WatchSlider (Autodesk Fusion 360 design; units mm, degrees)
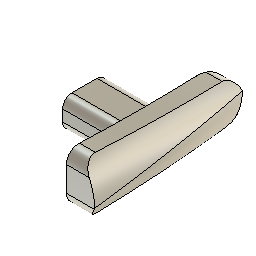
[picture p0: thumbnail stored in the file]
parameter "d65" = 4
sketch "Sketch1"
  line L1 (-0.2944, 8.4) -> (-0.2944, -8.4)
  line L2 (-2.6064, -5) -> (-2.6064, 5)
  line L3 (0, 0) -> (-120, 0)
  line L4 (2.7056, -8.4) -> (-0.2944, -8.4)
  line L5 (2.7056, 8.4) -> (-0.2944, 8.4)
  line L6 (-4.7, 1.75) -> (0, 1.75)
  line L7 (-4.7, -1.75) -> (-4.7, 1.75)
  line L8 (-0.0128, -1.75) -> (-4.7, -1.75)
  line L9 (-1.7, 0.75) -> (-4.7, 0.75)
  line L10 (-1.7, -0.75) -> (-1.7, 0.75)
  line L11 (-4.7, -0.75) -> (-1.7, -0.75)
  line L12 (0, 0) -> (-1.7, 0)
  line L13 (-1.7, 0) -> (-4.7, 0)
  arc A1 centre (-120, 0) radius 120 clockwise from (-0.2944, 8.4) to (-0.2944, -8.4)
  arc A2 centre (-120, 0) radius 117.5 clockwise from (-2.6064, 5) to (-2.6064, -5)
  arc A3 centre (-120, 0) radius 122.9928 clockwise from (2.7056, 8.4) to (2.7056, -8.4)
  circle C1 centre (-3.4, 0) radius 0.8
  circle C2 centre (-3.4, 0) radius 0.625
  point P2 (-0.2944, 8.4)
  point P3 (-0.2944, -8.4)
  point P5 (-2.6064, 5)
  point P6 (-2.6064, -5)
  point P18 (-1.7, 0.75)
  point P19 (-1.7, -0.75)
  point P20 (-4.7, -0.75)
  point P1 (0, 0)
  point P11 (2.7056, 8.4)
  dimension "d1" radius A1 = 120
  dimension "d2" distance A1 A2 = 2.5
  dimension "d3" distance P2 P3 = 16.8 (= "20 mm - 3.2 mm")
  dimension "d4" distance P5 P6 = 10
  dimension "d6" distance P18 P19 = 1.5
  dimension "d8" diameter C1 = 1.6
  dimension "d11" distance P19 P20 = 3
  dimension "d12" distance P1 L7 = 4.7
  dimension "d13" distance L6 L9 = 1
  dimension "d27" distance P2 P11 = 3
  dimension "d28" diameter C2 = 1.25
  dimension "d72" distance L7 C1 = 0.5
extrude "Extrude1" new body sketch "Sketch1" profile of A1 L6 L7 L8 L9 L10 L11 C1 distance 2.4
extrude "Extrude2" add sketch "Sketch1" profile of A1 L5 A3 distance 4
extrude "Extrude3" cut sketch "Sketch1" profile of L7 L9 L10 L11 C1 C2 distance 0.6
fillet "Fillet2" radius 0.75
sketch "Sketch4" plane through (0, -8.4, 0) normal (0, -1, 0) x axis (1, 0, 0)
  line L1 (2.7056, 2) -> (2.7056, -2)
  line L2 (-0.2944, 2) -> (2.7056, 2)
  line L3 (-0.2944, -2) -> (-0.2944, 2)
  line L4 (2.7056, -2) -> (-0.2944, -2)
  line L5 (1.4479, -2) -> (2.0264, -1.3106)
  line L6 (3.9, -2) -> (2.7056, -2)
  line L7 (3.9, 2) -> (3.9, -2)
  line L8 (2.7056, 2) -> (3.9, 2)
  arc A1 centre (-3.9717, -1.4642) radius 6 clockwise from (0.9273, 2) to (2.0264, -1.3106)
  point P6 (0.9273, 2)
  point P5 (-0.2944, -2)
  point P9 (1.4479, -2)
  point P7 (2.0264, -1.3106)
  dimension "d38" radius A1 = 6
  dimension "d39" distance L3 P6 = 1.2216
  dimension "d40" distance P5 P9 = 1.7422
  dimension "d41" angle L4 L5 = 50
  dimension "d42" distance P7 P9 = 0.9
sketch "Sketch5" plane through (0, 8.4, 0) normal (0, 1, 0) x axis (-1, 0, 0)
  line L1 (0.2944, 2) -> (0.2944, -2)
  line L2 (-2.7056, 2) -> (0.2944, 2)
  line L3 (-2.7056, -2) -> (-2.7056, 2)
  line L4 (0.2944, -2) -> (-2.7056, -2)
  line L5 (-1.2, 2) -> (-1.8, 1.6)
  line L6 (-3.9, 2) -> (-2.7056, 2)
  line L7 (-3.9, 2) -> (-3.9, -2)
  line L8 (-3.9, -2) -> (-3.9, 2)
  line L9 (-3.9, -2) -> (-2.7056, -2)
  arc A1 centre (3.5258, 1.6565) radius 5.3261 clockwise from (-0.3469, -2) to (-1.8, 1.6)
loft "Loft2" sketch "Sketch4" + "Sketch5"
extrude "Extrude4" cut sketch "Sketch1" profile of C2 no distance stored
sketch "Sketch6"
  line L1 (-0.2944, 6) -> (-0.2944, 8.4)
  line L2 (3.7056, 6) -> (-0.2944, 6)
  line L3 (3.7056, 8.4) -> (3.7056, 6)
  line L4 (-0.2944, 8.4) -> (3.7056, 8.4)
  line L5 (-0.2944, -6) -> (-0.2944, -8.4)
  line L6 (3.7056, -6) -> (-0.2944, -6)
  line L7 (3.7056, -8.4) -> (3.7056, -6)
  line L8 (-0.2944, -8.4) -> (3.7056, -8.4)
  point P2 (-0.2944, 8.4)
  point P5 (3.7056, 8.4)
  dimension "d32" distance P2 P5 = 4
  dimension "d33" distance L2 L6 = 12
extrude "Extrude5" cut sketch "Sketch6" no distance stored
fillet "Fillet3" radius 1
fillet "Fillet4" radius 1.6
sketch "Sketch10" plane through (-4.7, 0, 0) normal (-1, 0, 0) x axis (0, -1, 0)
  line L1 (-0.75, -0.3) -> (0.75, -0.3)
  line L2 (-0.75, 0.3) -> (-0.75, -0.3)
  line L3 (0.75, 0.3) -> (-0.75, 0.3)
  line L4 (0.75, -0.3) -> (0.75, 0.3)
  line L5 (1, -1.2) -> (-1, -1.2)
  line L6 (1.75, 0.45) -> (1.75, -0.45)
  line L7 (-1, 1.2) -> (1, 1.2)
  line L8 (-1.75, -0.45) -> (-1.75, 0.45)
  line L9 (0.4, 0.5) -> (-0.4, 0.5)
  line L10 (0.4, -0.5) -> (-0.4, -0.5)
  line L11 (0, 0) -> (0, -0.5)
  line L12 (0, 0) -> (-0.4, 0)
  arc A1 centre (-1, -0.45) radius 0.75 clockwise from (-1, -1.2) to (-1.75, -0.45)
  arc A2 centre (1, -0.45) radius 0.75 clockwise from (1.75, -0.45) to (1, -1.2)
  arc A3 centre (1, 0.45) radius 0.75 clockwise from (1, 1.2) to (1.75, 0.45)
  arc A4 centre (-1, 0.45) radius 0.75 clockwise from (-1.75, 0.45) to (-1, 1.2)
  arc A5 centre (-0.4, 0) radius 0.5 clockwise from (-0.4, -0.5) to (-0.4, 0.5)
  arc A6 centre (0.4, 0) radius 0.5 clockwise from (0.4, 0.5) to (0.4, -0.5)
  point P25 (0, 0)
  point P26 (-0.4, 0)
  dimension "d51" distance L9 L10 = 1
  dimension "d53" distance P25 P26 = 0.4
extrude "Extrude7" cut sketch "Sketch10" profile of L1 L2 L3 L4 A5 A6 L9 L10 against normal blind 3
sketch "Sketch13" plane through (0, 0, 2) normal (0, 0, 1) x axis (-1, 0, 0)
sketch "Sketch11" plane through (-4.7, 0, 0) normal (-1, 0, 0) x axis (0, -1, 0)
  line L1 (-0.4, -0.5) -> (0.4, -0.5)
  line L2 (0.4, 0.5) -> (-0.4, 0.5)
  line L3 (1, -1.2) -> (-1, -1.2)
  line L4 (1.75, 0.45) -> (1.75, -0.45)
  line L5 (-1, 1.2) -> (1, 1.2)
  line L6 (-1.75, -0.45) -> (-1.75, 0.45)
  line L7 (-5, 0.8946) -> (-11, 0.8946)
  line L8 (-5, -0.6054) -> (-5, 0.8946)
  line L9 (-11, -0.6054) -> (-5, -0.6054)
  line L10 (-11, 0.8946) -> (-11, -0.6054)
  line L11 (11, 0.8946) -> (5, 0.8946)
  line L12 (11, -0.6054) -> (11, 0.8946)
  line L13 (5, -0.6054) -> (11, -0.6054)
  line L14 (5, 0.8946) -> (5, -0.6054)
  line L15 (-6, -0.7108) -> (-6, 1)
  line L16 (-5, 0.1446) -> (-6, 0.1446)
  arc A1 centre (-0.4, 0) radius 0.5 clockwise from (-0.4, -0.5) to (-0.4, 0.5)
  arc A2 centre (0.4, 0) radius 0.5 clockwise from (0.4, 0.5) to (0.4, -0.5)
  arc A3 centre (-1, -0.45) radius 0.75 clockwise from (-1, -1.2) to (-1.75, -0.45)
  arc A4 centre (1, -0.45) radius 0.75 clockwise from (1.75, -0.45) to (1, -1.2)
  arc A5 centre (1, 0.45) radius 0.75 clockwise from (1, 1.2) to (1.75, 0.45)
  arc A6 centre (-1, 0.45) radius 0.75 clockwise from (-1.75, 0.45) to (-1, 1.2)
  point P30 (6, 1)
  point P20 (-11, 0.8946)
  point P23 (-11, -0.6054)
  dimension "d58" distance L10 L15 = 5
  dimension "d59" distance L8 L15 = 1
  dimension "d60" distance L14 P30 = 1
  dimension "d61" distance P20 P23 = 1.5
extrude "Extrude8" sketch "Sketch11" profile of L7 L8 L9 L10 L11 L12 L13 L14 L15 blind -1 from offset -0.7
sketch "Sketch12"
  line L1 (-0.1501, -6) -> (2.0884, -6)
  curve K1 (-0.1042, -5) -> (-0.1501, -6)
  line L2 (-4.7, -1.75) -> (-0.0128, -1.75)
  line L3 (-0.0128, 1.75) -> (-4.7, 1.75)
  line L4 (-4.7, 1.75) -> (-4.7, 1)
  line L5 (-4.7, 1) -> (-4.7, -1)
  line L6 (-4.7, -1) -> (-4.7, -1.75)
  curve K2 (0.0371, 5) -> (1.2548, 5.9778)
  curve K3 (1.2548, 5.9778) -> (1.5204, 6)
  line L7 (1.7863, 6) -> (1.5204, 6)
  line L8 (1.9645, 6) -> (1.7863, 6)
  curve K4 (1.9645, 6) -> (1.9752, 5.9836)
  curve K5 (1.9752, 5.9836) -> (2.1356, -6)
  line L9 (2.0884, -6) -> (2.1356, -6)
  curve K6 (1.9645, 10) -> (5.8514, 6.971)
  line L10 (1.9645, 10) -> (1.7863, 10)
  line L11 (1.7863, 10) -> (1.5204, 10)
  curve K7 (0.5908, 9.9223) -> (1.5204, 10)
  curve K8 (-3.671, 6.5) -> (0.5908, 9.9223)
  line L12 (-4.3567, -10) -> (2.0884, -10)
  line L13 (2.0884, -10) -> (5.9955, -10)
  curve K9 (5.9674, 6.2333) -> (5.9955, -10)
  line L14 (-7.7, -5.75) -> (-4.1426, -5.75)
  line L15 (-7.7, -1) -> (-7.7, -5.75)
  line L16 (-7.7, 1) -> (-7.7, -1)
  line L17 (-7.7, 5.75) -> (-7.7, 1)
  line L18 (6.1025, -7) -> (3.1025, -7)
  line L19 (-1.2056, -7) -> (-4.2056, -7)
  line L20 (-3.9145, 5.75) -> (-7.7, 5.75)
  curve K10 (-4.1426, -5.75) -> (-4.3567, -10)
  arc A1 centre (-120, 0) radius 120 clockwise from (-0.0786, 4.3421) to (-0.1042, -5)
  arc A2 centre (1.5204, 4.4) radius 1.6 clockwise from (-0.0786, 4.3421) to (0.0371, 5)
  arc A3 centre (1.5204, 4.4) radius 5.6 clockwise from (-3.9145, 5.75) to (-3.671, 6.5)
  arc A4 centre (1.9752, 5.9836) radius 4 clockwise from (5.8514, 6.971) to (5.9674, 6.2333)
  arc A5 centre (-1.2056, -7) radius 3 clockwise from (-1.2056, -10) to (-4.2056, -7)
  arc A6 centre (3.1025, -7) radius 3 clockwise from (6.1025, -7) to (3.1025, -10)
  dimension "d67" radius A6 = 3
  dimension "d68" distance L3 L20 = 4 (= "d65")
  dimension "d69" distance L2 L14 = 4 (= "d65")
  dimension "d70" distance L5 L15 = 3
mesh "Mesh1"
sketch "Sketch14" plane through (0, 0, 2) normal (0, 0, 1) x axis (-1, 0, 0)
  line L1 (-0.5499, -5.6721) -> (-0.5499, -11)
  line L2 (-0.5499, 11) -> (-0.5499, 6)
  curve K1 (0.1501, 6) -> (0.1042, 5)
  line L3 (0.1501, 6) -> (-0.5499, 6)
  arc A1 centre (120, 0) radius 120 clockwise from (0.0786, -4.3421) to (0.0128, -1.75)
  arc A2 centre (120, 0) radius 120 clockwise from (0.0128, 1.75) to (0.1042, 5)
  arc A3 centre (-1.5204, -4.4) radius 1.6 clockwise from (0.0786, -4.3421) to (-0.5499, -5.6721)
  arc A4 centre (120, 0) radius 120 clockwise from (0.0786, -4.3421) to (0.1042, 5)
  arc A5 centre (-1.5204, -4.4) radius 1.6 clockwise from (0.0786, -4.3421) to (-0.0371, -5)
named bodies: "WatchSlider"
